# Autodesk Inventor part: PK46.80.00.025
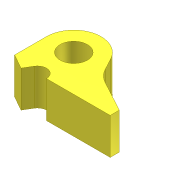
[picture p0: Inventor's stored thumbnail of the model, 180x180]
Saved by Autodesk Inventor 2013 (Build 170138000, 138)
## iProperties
Created: 2005-05
Part Number: PK46.80.00.025
Material: Steel, Mild
Document SubType Name: Modeling
Designer: salex
Manufacturer: Standard
Standards Organization: Custom
Density: 7.86 g/cm^3
Mass: 1312.57 g
Surface Area: 249.638 cm^2
Volume: 166.994 cm^3
Author: salex
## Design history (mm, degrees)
sketch "Эскиз1"
  geometry: L1 (-30, 0)-(-30, -35); L2 (-30, -35)-(-14, -44); L3 (-14, -44)-(-8.6, -34.898); L4 (10, -40)-(80, -40); L5 (80, -40)-(80, -30); L6 (80, -30)-(45.683, -11.363); L7 (33.53, 0.882)-(26.471, 14.118); L8 (-10.328, -30)-(13.832, -30); L9 (-230.71, 77.605)-(196.61, -162.182) reference; C1 r 15 at (0, 0); A1 r 30 centre (0, 0) between (26.471, 14.118) and (-30, 0); A2 r 10 centre (0, -40) between (10, -40) and (-8.6, -34.898); A3 r 30 centre (60, 15) between (33.53, 0.882) and (45.683, -11.363)
  constraints: 16 end point, 6 point on circle, 6 tangent, 4 centre point, 3 perpendicular, 1 coincident, 1 vertical, 1 other
  dimensions: "d0" = 30 radius of A1; "d1" = 30 diameter of C1; "d2" = 30 radius of A3; "d3" = 40 distance from line of C1.centre L4; "d4" = 10 distance of L4.end L5.end; "d5" = 80 distance from line of L5 C1.centre; "d6" = 60 horizontal distance of A3.centre C1.centre; "d7" = 55 distance from line of A3.centre L4; "d8" = 70 distance of L4.start L4.end; "d9" = 10 radius of A2; "d10" = 44 vertical distance of L2.end C1.centre; "d11" = 35 vertical distance of L1.end C1.centre; "d12" = 16 distance from line of L2.end L1; "d13" = 30 distance from line of C1.centre L8
extrude "Выдавливание1" new body sketch "Эскиз1" distance "d14" = 40; taper "d15" = 0 deg
body "Solid1"
node "ЗаимстЛин1"
